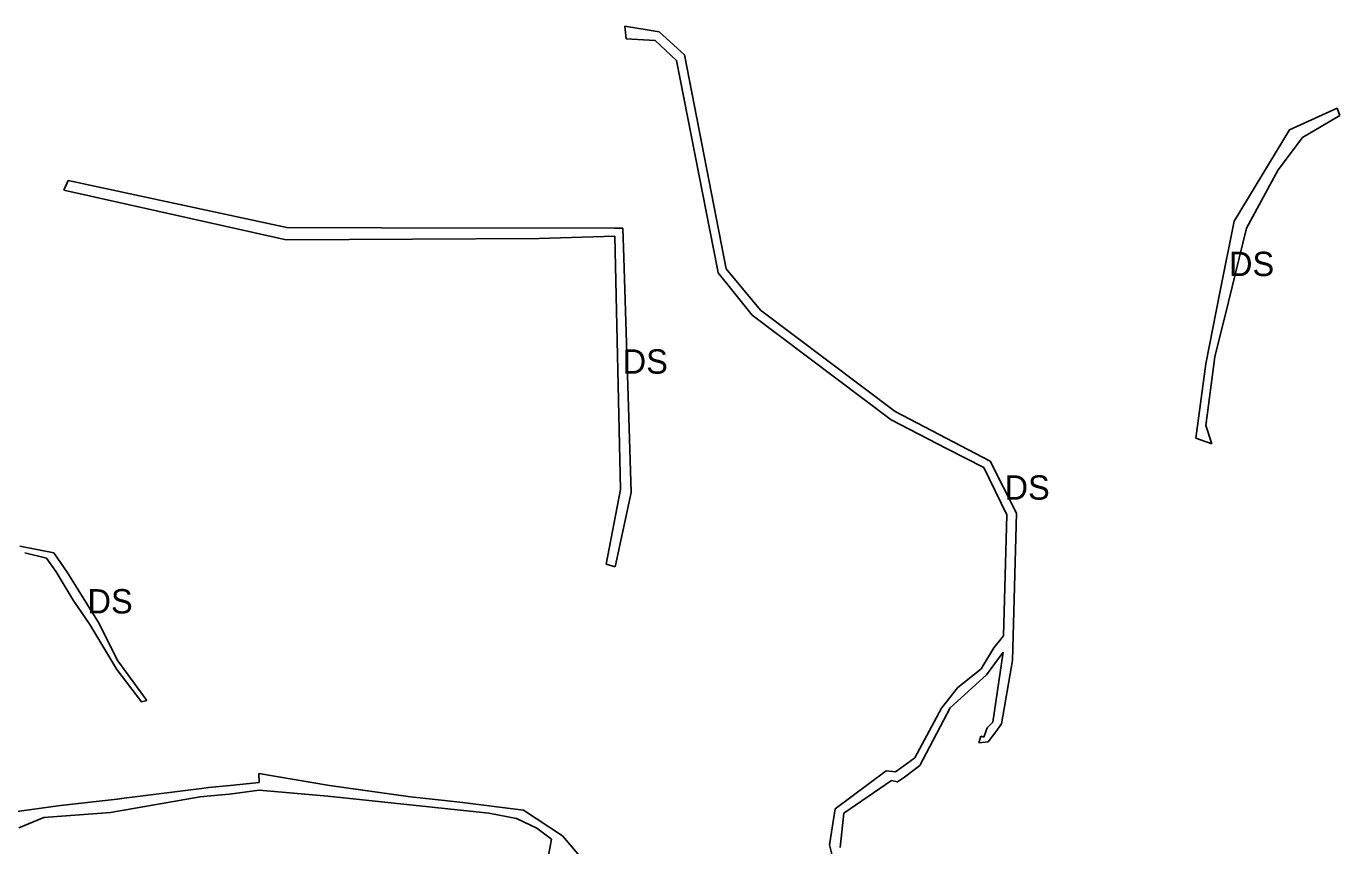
# Model space of a CAD drawing. Extents: x -477304 to -465641, y -1159113 to -1149285.
# Drawn here: x -472121.2 to -471635.5, y -1153308 to -1153005.2 of the extents above; entities that cross this region are included whole.
import ezdxf

# ---------------------------------------------------------------- set-up
doc = ezdxf.new("R2010")
doc.units = 0
doc.layers.add('35', color=7, linetype='Continuous')

msp = doc.modelspace()

# ---------------------------------------------------------------- linework, layer by layer
at = {"layer": '35'}
for p, q in [((-471899.88, -1153005.23), (-471899.4, -1153009.9)), ((-471862.4, -1153094.85), (-471877.84, -1153015.8)), ((-471649.36, -1153046.27), (-471635.54, -1153038.18)), ((-471635.54, -1153038.18), (-471636.48, -1153035.49)), ((-471658.31, -1153058.26), (-471649.36, -1153046.27)), ((-471670.01, -1153079.81), (-471658.31, -1153058.26)), ((-471989.83, -1153079.73), (-472024.82, -1153079.62)), ((-471903.66, -1153079.88), (-471989.83, -1153079.73)), ((-471900.62, -1153079.79), (-471903.66, -1153079.88)), ((-471900.2, -1153090.63), (-471900.62, -1153079.79)), ((-471674.52, -1153077.19), (-471679.83, -1153103.66)), ((-471676.7, -1153107), (-471670.01, -1153079.81)), ((-471931.66, -1153083.65), (-471903.59, -1153082.83)), ((-471903.59, -1153082.83), (-471901.49, -1153176.39)), ((-471897.55, -1153177.49), (-471900.2, -1153090.63)), ((-471849.74, -1153110.19), (-471862.4, -1153094.85)), ((-471799.97, -1153147.55), (-471849.74, -1153110.19)), ((-471681.71, -1153127.39), (-471676.7, -1153107)), ((-471685.04, -1153152.77), (-471681.71, -1153127.39)), ((-471764.8, -1153165.89), (-471799.97, -1153147.55)), ((-471682.83, -1153159.58), (-471685.04, -1153152.77)), ((-471688.75, -1153157.38), (-471682.83, -1153159.58)), ((-471901.49, -1153176.39), (-471906.82, -1153203.98)), ((-471903.47, -1153204.94), (-471897.55, -1153177.49)), ((-472110.95, -1153199.86), (-472123.6, -1153197.4)), ((-472121.68, -1153199.86), (-472113.74, -1153201.72)), ((-472113.74, -1153201.72), (-472110.09, -1153206.82)), ((-472106.01, -1153206.91), (-472110.95, -1153199.86)), ((-472110.09, -1153206.82), (-472103.82, -1153217.33)), ((-472094.53, -1153225.58), (-472106.01, -1153206.91)), ((-471906.82, -1153203.98), (-471903.47, -1153204.94)), ((-472087.33, -1153239.77), (-472094.53, -1153225.58)), ((-471759.92, -1153236.5), (-471763.82, -1153262.36)), ((-472076.57, -1153254.34), (-472087.33, -1153239.77)), ((-471760.54, -1153262.93), (-471756.56, -1153239.62)), ((-471765.51, -1153269.69), (-471762.74, -1153265.92)), ((-471762.74, -1153265.92), (-471760.54, -1153262.93)), ((-471768.23, -1153267.57), (-471769.03, -1153270.06)), ((-471769.03, -1153270.06), (-471765.51, -1153269.69)), ((-471767.07, -1153267.95), (-471768.23, -1153267.57)), ((-471792.65, -1153275.59), (-471796.71, -1153278.55)), ((-471803.19, -1153280.33), (-471822.09, -1153294.44)), ((-471799.73, -1153280.75), (-471803.19, -1153280.33)), ((-471796.71, -1153278.55), (-471799.73, -1153280.75)), ((-471796.5, -1153282.66), (-471790.76, -1153278.34)), ((-472009.01, -1153285.73), (-472035.15, -1153281.39)), ((-472035.15, -1153281.39), (-472035.04, -1153284.66)), ((-471979.16, -1153289.94), (-472009.01, -1153285.73)), ((-472087.52, -1153290.82), (-472108.5, -1153293.12)), ((-472084.97, -1153290.5), (-472087.52, -1153290.82)), ((-472056.36, -1153286.9), (-472084.97, -1153290.5)), ((-472053.77, -1153286.52), (-472056.36, -1153286.9)), ((-472048.96, -1153289.19), (-472046.09, -1153288.92)), ((-472046.09, -1153288.92), (-472035.01, -1153287.52)), ((-472035.01, -1153287.52), (-472009.67, -1153289.69)), ((-472009.67, -1153289.69), (-471950.09, -1153295.97)), ((-471960.91, -1153291.95), (-471979.16, -1153289.94)), ((-472108.5, -1153293.12), (-472126.45, -1153295.62)), ((-471822.09, -1153294.44), (-471824.15, -1153307.75)), ((-472123.94, -1153301.42), (-472114.62, -1153297.64)), ((-472114.62, -1153297.64), (-472090.01, -1153295.74)), ((-471932.35, -1153301.53), (-471927.02, -1153305.64)), ((-471913.74, -1153315.09), (-471922.97, -1153304.32)), ((-471927.02, -1153305.64), (-471936.35, -1153357.54)), ((-471824.15, -1153307.75), (-471818.75, -1153329.23))]:
    msp.add_line(p, q, dxfattribs=at)
for points in [[(-471877.84, -1153015.8), (-471887.2, -1153007.28), (-471899.88, -1153005.23)], [(-471899.4, -1153009.9), (-471888.67, -1153010.48), (-471880.75, -1153017.82), (-471865.58, -1153094.97)], [(-471636.48, -1153035.49), (-471654.06, -1153043.44), (-471674.52, -1153077.19)], [(-472024.82, -1153079.62), (-472105.67, -1153062.26), (-472107.23, -1153065.78)], [(-472107.23, -1153065.78), (-472025.06, -1153084.11), (-471931.66, -1153083.65)], [(-471865.58, -1153094.97), (-471865.35, -1153096.36), (-471852.81, -1153111.92)], [(-471679.83, -1153103.66), (-471685, -1153129.94), (-471688.75, -1153157.38)], [(-471852.81, -1153111.92), (-471801.4, -1153150.67), (-471780.9, -1153161.25)], [(-471780.9, -1153161.25), (-471767.08, -1153168.33), (-471758.67, -1153185.78)], [(-471756.56, -1153239.62), (-471755.05, -1153185.18), (-471764.8, -1153165.89)], [(-471758.67, -1153185.78), (-471759.88, -1153230.47), (-471763.4, -1153234.92), (-471768.15, -1153242.72), (-471776.87, -1153249.73), (-471782.78, -1153257.26), (-471792.65, -1153275.59)], [(-472103.82, -1153217.33), (-472097.7, -1153226.27), (-472087.69, -1153242.94), (-472078.57, -1153254.86), (-472076.57, -1153254.34)], [(-471790.76, -1153278.34), (-471779.62, -1153257.04), (-471766.11, -1153244.93), (-471759.92, -1153236.5)], [(-471763.82, -1153262.36), (-471765.94, -1153264.43), (-471767.07, -1153267.95)], [(-472035.04, -1153284.66), (-472045.74, -1153285.81), (-472053.77, -1153286.52)], [(-471820.29, -1153308.71), (-471818.89, -1153296.06), (-471801.22, -1153283.99)], [(-471801.22, -1153283.99), (-471799.08, -1153284.44), (-471796.5, -1153282.66)], [(-472090.01, -1153295.74), (-472056.93, -1153289.93), (-472048.96, -1153289.19)], [(-471922.97, -1153304.32), (-471937.39, -1153294.91), (-471960.91, -1153291.95)], [(-471950.09, -1153295.97), (-471939.97, -1153297.96), (-471932.35, -1153301.53)]]:
    msp.add_lwpolyline(points, dxfattribs=at)

# ---------------------------------------------------------------- texts
for p in [(-471676.48, -1153097.53), (-471900.67, -1153133.6), (-471759.48, -1153180.16), (-472098.54, -1153222.21)]:
    msp.add_text('DS', height=9, dxfattribs=at).set_placement(p)

doc.saveas('drawing.dxf')
